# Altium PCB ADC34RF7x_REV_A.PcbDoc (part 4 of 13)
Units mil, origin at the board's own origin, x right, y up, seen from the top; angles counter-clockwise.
Board outline 6250 x 2716.54 mil, 18 copper layers (Top Layer, L2 GND, L3 PWR, L4 GND, L5 PWR/SIG, L6 GND, L7 SIGNAL, L8 GND, L9 GND, L10 SIGNAL, L11 GND, L12 SIGNAL, L13 GND, L14 PWR, L15 GND, L16 PWR/SIG, L16 GND, Bottom Layer), stack 95.314 mil thick; 668 components, 786 nets, 3150 pads, 2020 vias.
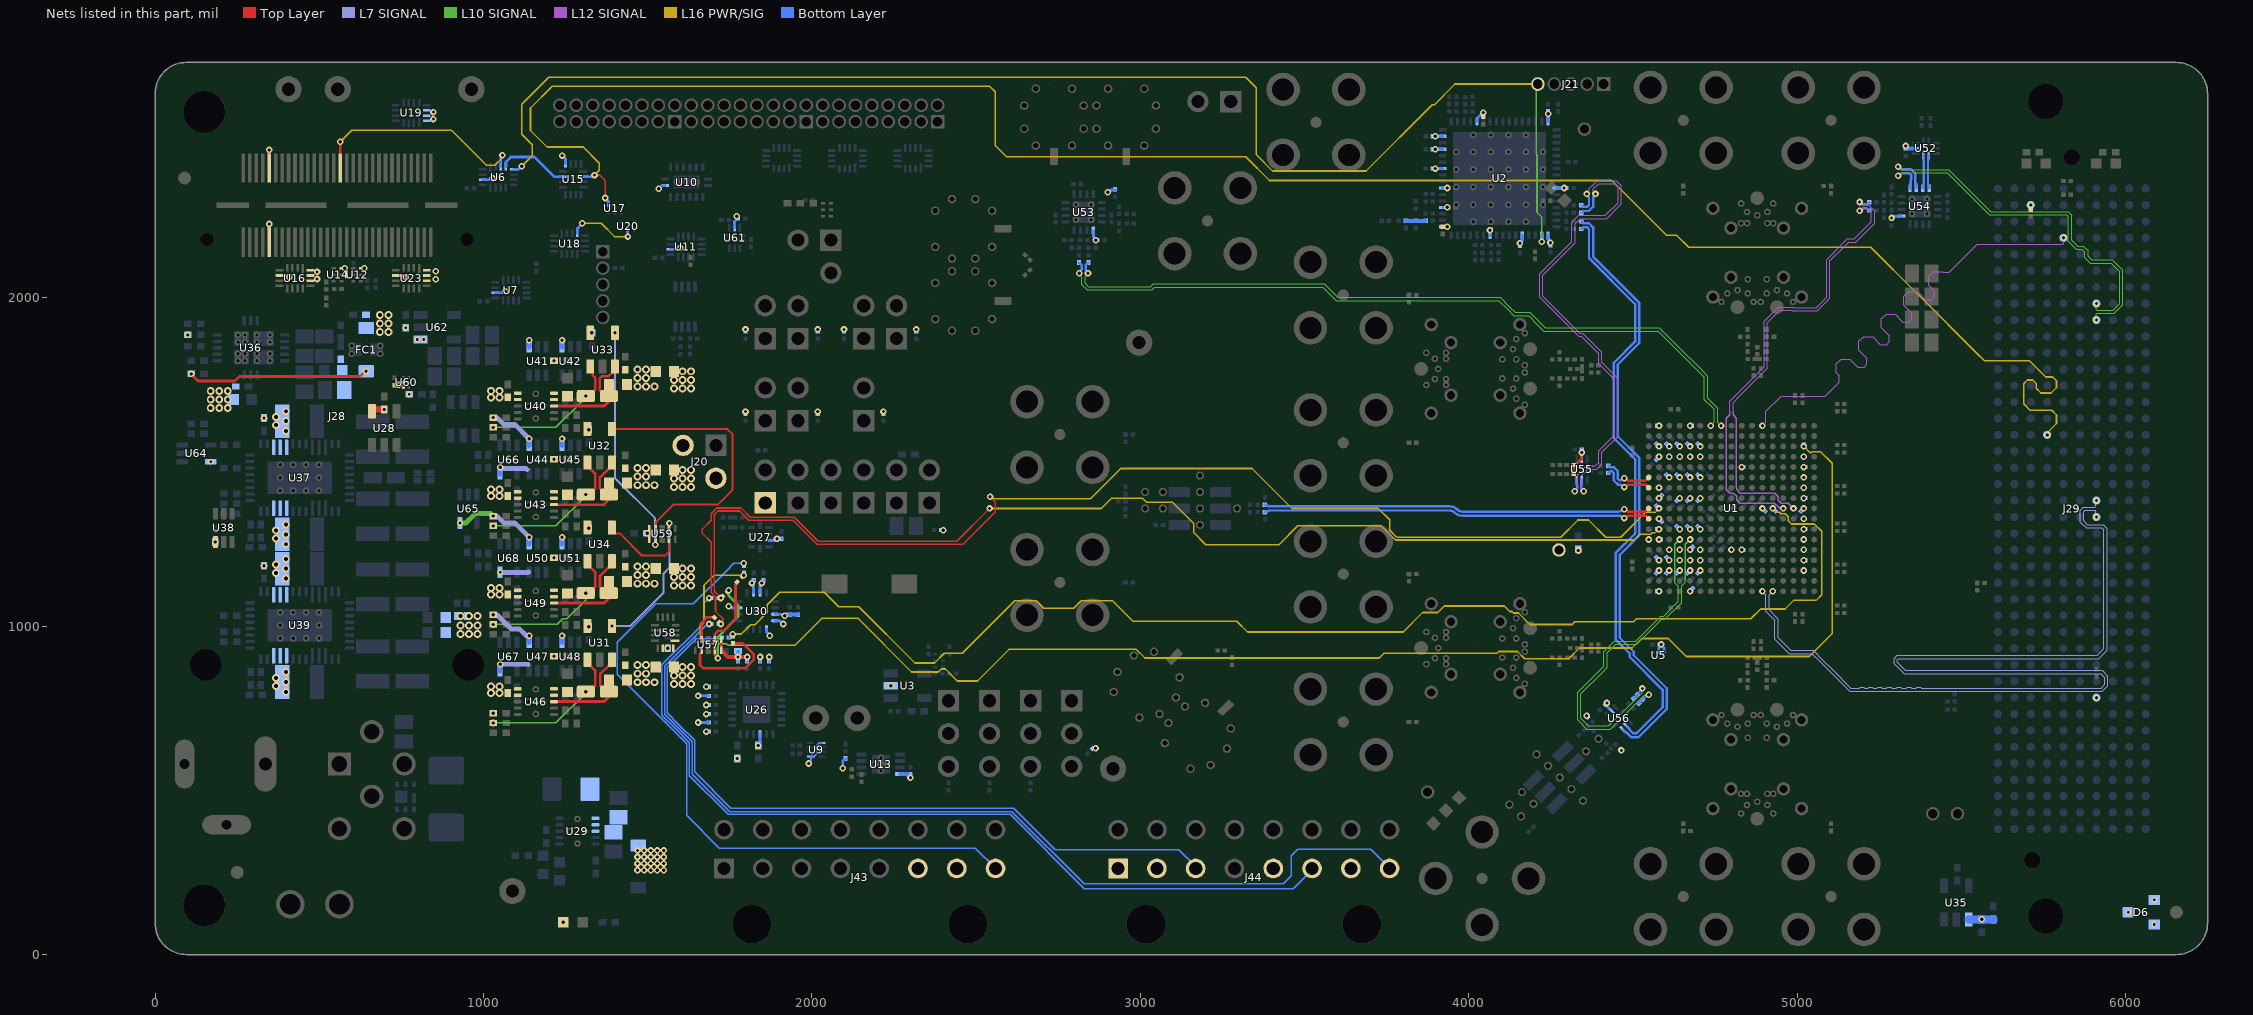
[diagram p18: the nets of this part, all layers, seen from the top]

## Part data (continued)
R202 R203: library part RSMD060312253, "RES 0 OHM JUMPER 0603 SMD", Manufacturer="Panasonic Electronic Components", Operating Temperature="-55°C ~ 155°C", Power (Watts)="0.1W, 1/10W", Ratings=AEC-Q200, Resistance="0 Ω", Supplier Part Number 1=10-ERJ-U030R00VCT-ND, Temperature Coefficient=±200ppm/°C, Tolerance=Jumper
R220 R221 R222 R223: library part RSMD080510615, "RES SMD 0 OHM JUMPER 1/8W 0805", Manufacturer="Panasonic Electronic Components", Operating Temperature="-55°C ~ 155°C", Power (Watts)="0.125W, 1/8W", Ratings=AEC-Q200, Resistance="0 Ω", Supplier Part Number 1=P0.0ACT-ND, Temperature Coefficient=-, Tolerance=Jumper
SH-J19 SH-J20 SH-J24 SH-J25 SH-J26 SH-J27 SH-J30 SH-J34 SH-J38 SH-J39 SH-J40 SH-J45: library part cmp00093, "2 (1 x 2) Position Shunt Connector Black Closed Top 0.100\" (2.54mm) Gold", Alt Manufacturer=-, Manufacturer=Sullins, Supplier Part Number 1=S9001-ND
SW1: library part cmp00291, "SWITCH TACTILE SPST-NO 0.05A 12V", Alt Manufacturer=-, Manufacturer="Würth Elektronik", Supplier Part Number 1=732-7053-1-ND
SW2 SW3 SW4 SW6: library part cmp00353, "Switch Slide SPDT 12V, 500mA", Alt Manufacturer=-, Manufacturer="Wurth Elektronik", Supplier Part Number 1=710-450301014042
T1 T2 T4 T5: library part cmp00063, "Broadband Balun, 500 kHz to 6 GHz", Alt Manufacturer=-, Manufacturer="Marki Microwave"
T3: library part cmp00422, "1:2 CORE & WIRE Transformer, 30 - 6000 MHz, 50Ω", Alt Manufacturer=-, Manufacturer=Mini-Circuits, Supplier Part Number 1=139-TCM2-63WX
T6: library part cmp00381, "1:2 CORE & WIRE Transformer, 10 - 4000 MHz, 50Ω", Alt Manufacturer=-, Manufacturer=Mini-Circuits, Supplier Part Number 1=139-TCM2-43X
TP3: library part cmp00053, "Test Point, Miniature, Orange, TH", Alt Manufacturer=-, Color=Orange, Manufacturer=Keystone, Supplier Part Number 1=36-5003-ND
TP4 TP5 TP9 TP10: library part cmp00051, "Test Point, Miniature, Black TH", Alt Manufacturer=-, Color=Black, Manufacturer=Keystone, Supplier Part Number 1=36-5001-ND
TP6 TP7 TP8: library part cmp00052, "Test Point, Miniature, White, TH", Alt Manufacturer=-, Color=White, Manufacturer=Keystone, Supplier Part Number 1=36-5002-ND
TP11: library part cmp00040, "Test Point, Multipurpose, Red, TH", Alt Manufacturer=-, Color=Red, Manufacturer=Keystone, Supplier Part Number 1=36-5010-ND
TP12: library part cmp00047, "Test Point, Multipurpose, Brown, TH", Alt Manufacturer=-, Color=Brown, Manufacturer=Keystone, Supplier Part Number 1=36-5125-ND
U1: "Quad channel 16-bit 1.5 GSPS RF sampling data converter, FCCSP-289 (ANH0289A)", Alternate Manufacturer="Texas Instruments"
U2: library part cmp00252, "Ultra low-noise JESD204B compliant clock jitter cleaner with integrated 2370 to 2630-MHz VCO0", Alt Manufacturer="Texas Instruments", Alt PartNumber=LMK04828BISQE/NOPB, Color=-, Supplier Part Number 1=296-40278-1-ND
U3: "Open Drain, 1.6V threshold, Nano Power, Wide VIN Voltage Detector with Programmable Delay", Alt Manufacturer=-, Manufacturer="Texas Instruments"
U4: library part cmp00518, "Low-Power Single 2-Input Positive-AND Gate", Color=-, Manufacturer="Texas Instruments", PartNumber=SN74AUP1G08DRYR, Supplier Part Number 1=296-SN74AUP1G08DRYRCT-ND
U5 U60: library part cmp00348, "±0.1°C accurate digital temperature sensor with integrated NV memory, YBG0006AJAP (DSBGA-6)", Alt Manufacturer=-, Manufacturer="Texas Instruments"
U6: "Low-Voltage 4-Bit 1-of-2 FET Multiplexer/Demultiplexe", Color=-, Manufacturer="Texas Instruments", PartNumber=SN74CBTLV3257RSVR, Supplier Part Number 1=296-35586-1-ND
U7 U11: library part SN74CBTLV3257RSV, "Low-Voltage 4-Bit 1-of-2 FET Multiplexer/Demultiplexe", Color=-, Manufacturer="Texas Instruments", Supplier Part Number 1=296-35586-1-ND
U8: library part cmp00344, "Low-Power Single Bus Buffer Gate With Tri-State Output", Alt Manufacturer="Texas Instruments", Color=-
U9: "2-BIT BIDIRECTIONAL VOLTAGE-LEVEL TRANSLATOR, DQE0008A (X2SON-8). Open drain friendly", Alternate Manufacturer="Texas Instruments"
U10: "Bidirectional 4:1, 2-Channel Multiplexer with Injection Current Control", Manufacturer="Texas Instruments"
U12 U14 U17 U20: library part cmp00343, "Low-Power Single Bus Buffer Gate With 3-State Output", Alt Manufacturer="Texas Instruments", Alt PartNumber=SN74LVC1G125DRYT, Color=-
U13: library part cmp00154, "EEPROM 64K 8KX8 1.8V SER EE IND 1/4AWP RPO", Alt Manufacturer=-, Manufacturer=Microchip, Supplier Part Number 1=24LC64FT-I/MNYCT-ND
U15 U16 U18 U19 U22 U23 U24 U25: library part cmp00171, "Translation - Voltage Levels 4-bit dual-supply bus transceiver with 3-state outputs and independent direction control inputs", Alt Manufacturer="Texas Instruments", Alt PartNumber=SN74AXC4T774RSV, Color=-, Supplier Part Number 1=296-24741-1-ND
U21: library part cmp00175, "Dual-Bit Dual-Supply Bus Transceiver With Configurable Voltage Translation And 3-State Outputs", Alt Manufacturer="Texas Instruments", Alt PartNumber=SN74AXCH2T45DCU, Color=-, PartNumber=SN74AVCH2T45DCU
U26: library part CMP-0076018-3, "Low-Voltage 8-Channel I2C Switch With Reset, RGE0024C (VQFN-24)", Alternate Manufacturer="Texas Instruments", Operating Temperature Range="-40 to 85 C"
U27: library part CMP-0081816-1, "16-Bit 860SPS 1-Ch Delta-Sigma ADC With PGA, Oscillator, VREF, Comparator, and I2C, RUG0010A (X2QFN-10)", Alternate Manufacturer="Texas Instruments", Alternate PartNumber=ADS1114IRUGT, Operating Temperature Range="-40 to 125 C", Rating=Catalog
U28 U31 U32 U33 U34: "26V, 350kHz current sense amplifier", Alt Manufacturer="Texas Instruments", Alt PartNumber=INA180B1IDBVT
U29: library part cmp00157, "12V, 5A, 30mΩ eFuse with Adjustable +/-15% Accurate Current Limit, DRC0010J (VSON-10)", Alt Manufacturer=-, Manufacturer="Texas Instruments"
U30: "16-Bit, 4-Channel, 1-kSPS, Delta-Sigma ADC with I2C Interface, RTE0016D (WQFN-16)", Alternate Manufacturer="Texas Instruments", Alternate PartNumber=ADS1119IRTET, Operating Temperature Range="-40 to 125 C"
U35 U62: "150-mA, 30-V, ultra-low-IQ, low-dropout voltage regulator with reverse current protection and enable", Alt Manufacturer=-, Manufacturer="Texas Instruments", Supplier Part Number 1=296-35484-1-ND
U36: library part cmp00201, "3-V to 17-V, 2-A/3-A Low-Noise and Low-Ripple Buck Power Module with Integrated Ferrite Bead Filter Compensation", Alt Manufacturer=-, Manufacturer="Texas Instruments", Max Supply Voltage=17V, Min Supply Voltage=3V, Nominal Supply Current=5mA, Operating Temperature Range="-55°C to +125°C", Output Voltage=0.8-5.5V, PartNumber=TPSM82913RDU, Switching Frequency=1/2.2MHz
U37 U39: library part cmp00235, "4.5-V to 15-V Input, Dual 6-A / Single 12-A Output Power Module", Alt Manufacturer=-, Manufacturer="Texas Instruments", Supplier Part Number 1=296-TPSM5D1806RDBRCT-ND
U38 U41 U44 U47 U50: "128-tap single-channel digital potentiometer (digipot) with I2C interface (address 0101110)", Alt Manufacturer=-, Alternate Manufacturer="Texas Instruments", Alternate PartNumber=TPL0401A-10DCKT
U40 U43 U46 U49: library part cmp00446, "2-A, ultra-low noise ultra-high PSRR RF voltage regulator", Alt Manufacturer=-, Manufacturer="Texas Instruments", PartNumber=TPS7A9601DSCR
U42 U45 U48 U51: "128-tap single-channel digital potentiometer (digipot) with I2C interface (address 0111110)", Alt Manufacturer=-, Alternate Manufacturer="Texas Instruments", Alternate PartNumber=TPL0401B-10DCKT
U52 U55 U56: library part TMUX121NKGR, "2-pF, 3.3-V, 2:1 (SPDT), 2-channel, switch with 1.8-V compatible logic", Manufacturer="Texas Instruments"
U53 U54: library part cmp00271, "Texas Instruments", Color=-, Manufacturer_Part_Number=LMK1D1204RGTR, PartNumber=LMK1D1204RGTT, Supplier Part Number 1=296-LMK1D1204RGTRCT-ND
U57 U59: "3-pA on-state leakage current, 5-V, 4:1, 1-channel precision multiplexer", Alt Manufacturer=-, Manufacturer="Texas Instruments", Supplier Part Number 1=296-53437-2-ND
U58: "Low-voltage 8-bit I²C-bus/SMBus I/O expander with interrupt, reset and agile I/O configuration", Alt Manufacturer=-, Manufacturer="Texas Instruments", Supplier Part Number 1=296-TCAL9538RSVRTR-ND
U61: "2-pF, 3.3-V, 2:1 (SPDT), 2-channel, switch with 1.8-V compatible logic", Manufacturer="Texas Instruments"
U63: "3 Rail Simple Power Sequencer with Fixed Time Delay", Manufacturer="Texas Instruments"
U64 U65 U66 U67 U68: library part cmp00268, "SN74AUP1G08 Low-Power Single 2-Input Positive-AND Gate", Color=-, Manufacturer="Texas Instruments", Supplier Part Number 1=296-19075-1-ND
ZZ1: library part CMP-0003616-3
ZZ2: library part CMP-0077236-1
ZZ3: library part CMP-0077237-1
ZZ4: library part CMP-0077238-1

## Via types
v1: diameter 20, hole 10, Top Layer to Bottom Layer, tented both sides, 1793 vias
v2: diameter 24, hole 12, Top Layer to Bottom Layer, tented both sides, 168 vias
v3: diameter 18, hole 8, Top Layer to Bottom Layer, tented both sides, 59 vias

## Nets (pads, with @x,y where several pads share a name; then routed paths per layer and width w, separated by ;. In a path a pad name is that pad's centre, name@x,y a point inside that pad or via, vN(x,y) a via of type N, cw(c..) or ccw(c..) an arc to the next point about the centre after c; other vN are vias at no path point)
2p3V: C221.2 C222.2 C228.2 C235.2 C242.2 C249.2 FB4.2 FB5.2 U40.1 U40.2 U43.1 U43.2 U46.1 U46.2 U49.1 U49.2
  other v2: 1022.37,796.58 1048.37,796.58 1022.37,816.58 1048.37,816.58 929.64,975.59 955.64,975.59 981.64,975.59 929.64,1002.01 955.64,1002.01 981.64,1002.01 929.64,1030.43 955.64,1030.43 981.64,1030.43 1022.37,1096.58 1048.37,1096.58 1022.37,1116.58 1048.37,1116.58 1022.37,1396.58 1048.37,1396.58 1022.37,1416.58 1048.37,1416.58 1022.37,1696.58 1048.37,1696.58 1022.37,1716.58 1048.37,1716.58
3p3V: C170.1 FB1.2 FC1.1 R112.2 R114.2 | length 553.3
  Top Layer w9: v1(109.72,1767.95) 130.88,1746.8 243.05,1746.8 256.6,1760.34 623.9,1760.34 639.26,1775.71 v1(642.24,1775.71)
3p3V_AUX: D6.1 J29.D32
  other v1: 5911.42,782.27
  other v3: 6087.6,166.23
3p3V_EEPROM: C181.2 D6.3 R211.1 U13.8 | length 80.3
  Bottom Layer w8: v1(2094.07,567.32) 2094.07,589.15 2098.76,593.83 2100.15,593.83 2102.45,596.13 R211.1@2102.45,596.92 ; v1(2299.91,538.04) C181.2@2299.91,548.04
  Bottom Layer w12: U13.8@2268.5,550 2287.96,550 v1(2299.91,538.04)
  other v3: 6008.86,128.83
3p3V_Utility: C41.1 C42.1 C43.1 C44.1 C45.1 C46.1 C47.1 C48.1 C49.1 C50.1 C51.1 C52.1 C61.2 C94.1 C102.1 C103.1 C104.1 C106.1 C107.1 C175.1 C176.1 C177.1 C178.2 C179.2 C182.2 C183.2 C185.2 C186.2 C204.2 C215.2 C233.2 C240.2 C247.2 C254.2 C256.2 C258.2 C263.2 C264.2 D6.2 FC1.3 J28.51 J28.52 J38.1 R66.2 R67.2 R71.2 R72.2 R73.2 R74.2 R79.1 R88.2 R92.2 R93.2 R94.2 R95.2 R96.2 R97.2 R98.2 R99.2 R100.2 R101.2 R102.2 R118.1 R125.1 R131.2 R137.2 R143.2 R149.2 R162.2 R165.2 R189.2 R190.2 R191.2 R192.2 R210.2 R215.2 U2.10 U2.17 U2.21 U2.26 U2.33 U2.36 U2.39 U2.42 U2.45 U2.47 U2.53 U2.64 U5.B1 U5.C1 U6.14 U7.14 U9.1 U9.5 U10.16 U11.14 U12.6 U14.6 U15.13 U16.6 U16.14 U16.15 U16.16 U19.14 U19.15 U19.16 U23.6 U23.14 U23.15 U23.16 U26.21 U27.8 U28.5 U30.1 U30.7 U30.10 U30.11 U30.15 U30.16 U31.5 U32.5 U33.5 U34.5 U38.1 U41.1 U42.1 U44.1 U45.1 U47.1 U48.1 U50.1 U51.1 U52.9 U53.5 U54.5 U55.9 U56.9 U57.5 U57.6 U58.1 U58.14 U58.15 U58.16 U59.5 U59.6 U60.B1 U60.C1 U61.9 U64.5 U65.5 U66.5 U67.5 U68.5 | length 2945.1
  Top Layer w8: U16.6@378.7,2067.76 400.45,2067.76 405.45,2062.76 v1(408.7,2062.76) ; U14.6@567.36,2089.41 v1(577.36,2089.41) ; U12.6@627.05,2089.41 v1(637.05,2089.41) ; C178.2@729.29,1733.83 729.58,1734.12 740.84,1734.12 v1(741.13,1734.41) ; U23.6@733.03,2067.76 754.78,2067.76 759.78,2062.76 v1(763.03,2062.76) ; U59.6@1505.18,1264.12 1505.18,1271.18 1500.48,1275.87 1500.48,1280.52 v1(1498.19,1282.81) 1498.19,1282.94 1505.18,1289.93 U59.5@1505.18,1296.99 ; U57.6@1723.88,959.19 U57.5@1723.88,926.32 1723.88,923.26 U57.5@1725.94,921.2 ; C42.1@3920.96,2216.02 v1(3935.05,2216.04) ; C47.1@4044.13,2550.8 v1(4044.13,2563.74) v1@4044.13,2564.74 ; R190.2@4319.91,1463.74 R189.2@4319.91,1490.75 4324.89,1490.75 4343.25,1509.1 4343.25,1527.35 v1(4344.64,1528.74) ; v1@5331.04,2454.89 v1@5331.04,2461.96 ; v1(741.13,1734.41) 743.42,1732.11 750.49,1732.11 756.37,1726.23 U60.C1@756.65,1726.23 U60.B1@756.65,1741.98 756.37,1741.98 751.09,1736.7 743.42,1736.7 v1(741.13,1734.41)
  Top Layer w11: J28.52@347.2,2169.41 v1(347.2,2224.41) ; J28.51@347.2,2395 v1(347.2,2450)
  Top Layer w12: U57.5@1725.94,921.2 1729,921.2 1744.25,905.95 v1(1775.05,905.95) v1(1802.74,905.95)
  Top Layer w20: U28.5@660.5,1654.13 660.5,1659.88 v1(697.55,1659.88)
  L7 SIGNAL w15: v1(1030,1035) 1030.96,1034.04 1042.32,1034.04 1085.39,990.97 1110.3,990.97 1129.84,971.43 1138.18,971.43 v1(1139.13,970.47) ; v1(1030,1335) 1030.96,1334.04 1042.32,1334.04 1061.86,1314.5 1095.11,1314.5 v1(1139.13,1270.47) ; v1(1030,1635) 1030.96,1634.04 1042.32,1634.04 1061.86,1614.5 1095.11,1614.5 v1@1138.18,1571.43 ; v1(1050.63,883.86) 1135.66,883.86 1136.22,883.3 ; v3(1050.63,1163.86) 1136.22,1163.86 1136.85,1164.49 ; v1@1050.63,1480.18 1129,1480.18 1131.98,1477.19
  L10 SIGNAL w15: v3(928.31,1314) 945.89,1314 974.44,1342.56 1022.44,1342.56 v1(1030,1335)
  Bottom Layer w4: R79.1@2855,627.06 2855.61,627.06 2856.31,627.76 v1(2863.7,627.76)
  Bottom Layer w6: v1(1990.28,581.72) 1990.28,584.72 1997.39,591.83 U9.1@1997.39,602.63 2005.64,602.63 2013.51,610.49 2013.51,636.33 2021.09,643.91 2030.8,643.91 U9.5@2030.85,643.96
  Bottom Layer w8: U6.14@997.49,2359.25 1019.25,2359.25 1024.25,2364.25 v1(1027.49,2364.25) ; U7.14@1036.12,2015 1057.87,2015 1062.87,2020 v1(1066.12,2020) ; v1(1239.74,2432.87) 1239.74,2432.09 1242.04,2429.79 1242.82,2429.79 1249.74,2422.87 U15.13@1249.74,2407.87 ; v1(1533.39,2332.09) 1534.8,2332.09 1544.07,2341.36 1552.66,2341.36 U10.16@1553.39,2342.09 ; U11.14@1569.13,2147.28 1590.89,2147.28 1595.89,2152.28 v1(1599.13,2152.28) ; v1(1653.34,706.47) 1673.34,706.47 R93.2@1685.43,706.48 ; v1(1653.34,787.52) 1673.34,787.52 R96.2@1685.43,787.54 ; R92.2@1678.36,678.8 R92.2@1685.43,678.8 ; R94.2@1678.36,732.17 R94.2@1685.43,732.17 ; R95.2@1678.35,759.84 R95.2@1685.43,759.85 ; R97.2@1678.36,815.22 R97.2@1685.43,815.22 ; U61.9@1764.47,2213.57 1764.47,2232.47 1773.67,2241.68 C182.2@1774.46,2241.68 1771.45,2244.7 v1(1771.45,2247.74) ; R98.2@1775.07,892.86 R98.2@1775.07,899.93 ; v1(1775.05,905.95) C176.1@1775.05,923.95 ; R165.2@1797.76,1647.41 v1(1797.76,1653.41) ; R73.2@1797.76,1897.41 v1(1797.76,1903.41) ; R99.2@1802.75,892.86 R99.2@1802.75,899.93 ; R100.2@1842.12,892.86 R100.2@1842.12,899.93 ; R101.2@1869.81,892.86 R101.2@1869.81,899.93 ; R162.2@2017.76,1647.41 v1(2017.76,1653.41) ; R74.2@2017.76,1897.41 v1(2017.76,1903.41) ; R72.2@2097.76,1897.41 v1(2097.76,1903.41) ; R88.2@2217.76,1647.41 v1(2217.76,1653.41) ; R71.2@2317.76,1897.41 v1(2317.76,1903.41) ; R215.2@2394.27,1292.17 v1(2400.27,1292.17) ; C44.1@3890.96,2393.19 v1(3898.05,2393.2) ; C45.1@3890.96,2452.24 v1(3898.05,2452.26) ; C46.1@3890.96,2491.61 v1(3898.05,2491.63) ; U2.33@3928.03,2216.02 U2.33@3920.96,2216.02 v1(3935.05,2216.04) ; U2.36@3928.03,2275.08 U2.36@3920.96,2275.08 v1(3935.05,2275.09) ; U2.39@3928.03,2334.13 U2.39@3920.96,2334.13 v1@3935.04,2334.14 ; U2.53@4025.29,2536.89 4026.21,2537.81 4026.21,2546.83 v1@4044.13,2564.74 ; C52.1@4156.08,2158.43 v1(4156.07,2165.52) ; v1(4241.84,2559.8) C49.1@4241.82,2566.89 ; C51.1@4248.82,2160.43 v1(4248.81,2167.52) ; v1(4290.33,2334.12) C48.1@4297.42,2334.13 ; U55.9@4344.64,1508.74 v1(4344.64,1528.74) C263.2@4344.64,1538.27 ; v1(4358.93,726.7) R191.2@4361.93,723.7 ; C264.2@4415.91,760.86 v1(4420.91,765.88) ; C264.2@4418.08,763.06 4417.56,762.53 4417.56,759.26 U56.9@4429.5,747.32 ; C264.2@4420.91,761.42 v1(4420.91,765.88) ; R192.2@4462.07,624.52 v1(4465.07,621.52) ; U5.B1@4578.88,919.29 4578.88,933.6 C179.2@4586.75,941.48 ; C179.2@4581.75,944.29 v1(4586.75,944.29) C179.2@4586.75,941.48 ; U5.C1@4594.63,919.29 4594.63,933.6 C179.2@4586.75,941.48 ; v1(5287.73,2243) 5288.94,2243 5294.52,2248.58 U54.5@5317.73,2248.58
  Bottom Layer w9: v1(1747.16,1060.85) 1750.14,1060.85 1755.14,1055.85 U30.7@1777.16,1055.85 ; U30.10@1822.44,1101.13 1822.44,1123.15 1817.44,1128.15 v1(1817.44,1131.13) 1817.44,1133.15 1823.1,1138.82 C185.2@1823.1,1139.6 ; v1(1837,636.2) 1842.12,641.32 U26.21@1842.12,671.2 ; U30.11@1842.12,1101.13 1842.12,1123.15 1847.12,1128.15 v1(1847.12,1131.13) 1847.12,1133.15 1852.79,1138.82 C186.2@1852.79,1139.6 ; U30.1@1861.81,990.89 1861.89,990.8 1861.89,981.8 1871.81,971.89 v1(1871.81,970.89) ; U27.8@1868.71,1261.07 1885.74,1261.07 1890.74,1266.07 v1(1893.71,1266.07) C183.2@1907.71,1266.07 ; U30.16@1887.4,1016.48 1887.48,1016.39 1901.49,1016.39 1911.4,1006.48 v1(1912.4,1006.48) ; U30.15@1887.4,1036.17 1909.42,1036.17 1914.42,1031.17 v1(1917.4,1031.17) ; U53.5@2856.85,2205.32 2856.85,2185.78 2864.34,2178.29 v1(2864.34,2175.32) C61.2@2869.34,2175.32
  Bottom Layer w10: v1(2900.65,2321.19) 2903.35,2321.19 2909.91,2327.74 2921.66,2327.74 2922.96,2329.04 R210.2@2922.96,2329.83 ; v1@3898.06,2393.19 U2.42@3920.96,2393.19 ; v1@3898.06,2452.24 U2.45@3920.96,2452.24 ; v1@3898.06,2491.61 U2.47@3920.96,2491.61 ; U2.26@4064.66,2190.43 v1(4064.66,2205.43) v1@4064.66,2210.43 ; v1(4156.07,2165.52) 4156.07,2168.22 4163.08,2175.24 U2.21@4163.08,2190.43 ; U2.17@4241.82,2190.43 4241.82,2177.21 4248.81,2170.22 v1(4248.81,2167.52) ; U2.64@4241.82,2536.89 v1(4241.84,2559.8) ; U2.10@4267.42,2334.13 v1(4290.33,2334.12)
  Bottom Layer w12: v1(1917.4,1031.17) 1919.56,1031.17 1923.38,1034.98 R66.2@1932.4,1034.98 R67.2@1957.4,1034.98 ; C256.2@5331.04,2454.89 U52.9@5361.04,2454.89
  Bottom Layer w15: U67.5@1050.63,863.86 v1(1050.63,883.86) ; U66.5@1050.63,1463.86 v1(1050.63,1483.86) ; U47.1@1139.13,950.47 v1(1139.13,970.47) ; U50.1@1139.13,1250.47 v1(1139.13,1270.47) ; U44.1@1139.13,1550.47 v1(1139.13,1570.47) ; U41.1@1139.13,1850.47 v1(1139.13,1870.47) ; U48.1@1239.13,950.47 v1(1239.13,970.47) ; U51.1@1239.13,1250.47 v1(1239.13,1270.47) ; U45.1@1239.13,1550.47 v1(1239.13,1570.47) ; U42.1@1239.13,1850.47 v1(1239.13,1870.47)
  other v1: 1773.07,596.83 1678.34,678.78 1678.34,732.15 1030,735 1678.34,759.83 1678.34,815.21 1842.11,905.95 1869.79,905.95 1214.61,907.95 1561.46,932.35 1320.5,998.21 331.53,1184.01 1214.61,1207.95 183.42,1255.95 1320.5,1298.21 1214.61,1507.95 1320.5,1598.21 331.53,1633.5 1214.61,1807.95 1329.5,1893.21 854.82,2056.26 493.19,2057.01 493.19,2078.5 854.82,2080.26 3935.05,2334.15 5331.05,2461.98 847.52,2543.94 847.52,2565.43
  other v2: 684.2,1895.3 710.2,1895.3 684.2,1921.3 710.2,1921.3 684.2,1947.3 710.2,1947.3
  other v3: 6087.6,91.43 169.01,1500.59
12V: C58.2 C95.2 C96.2 C126.2 C128.1 C171.2 C172.2 C173.2 C174.2 D3.1 D5.1 F1.1 R113.1 R179.2 R224.2 R225.1 U29.6 U29.7 U29.8 U35.1 U36.18 U37.4 U37.5 U37.6 U37.33 U37.34 U37.35 U39.4 U39.5 U39.6 U39.33 U39.34 U39.35 U62.1 | length 75.1
  Bottom Layer w24: U35.1@5522.4,107 v1(5562.52,107) R179.2@5597.52,107
  other v1: 1243.15,98.59 1469,257 1489,257 1509,257 1529,257 1549,257 1469,277 1489,277 1509,277 1529,277 1549,277 1469,297 1489,297 1509,297 1529,297 1549,297 1469,317 1489,317 1509,317 1529,317 1549,317 99.72,1886.69
  other v2: 397.94,799.76 367.94,817.26 397.94,829.76 367.94,842.26 397.94,859.76 397.94,1144.8 367.94,1162.3 397.94,1174.8 367.94,1187.3 397.94,1204.8 397.94,1249.25 367.94,1266.75 397.94,1279.25 367.94,1291.75 397.94,1309.25 397.94,1594.29 367.94,1611.79 397.94,1624.29 367.94,1636.79 397.94,1654.29 169.26,1663.64 195.26,1663.64 221.26,1663.64 169.26,1689.64 195.26,1689.64 221.26,1689.64 169.26,1715.64 195.26,1715.64 221.26,1715.64
  other v3: 773.6,1705.75 798.07,1872.9 818.07,1872.9 763.07,1908.33
\M2C-PRESENT: J29.H2 R86.2 | length 14
  Top Layer w8: R86.2@5711.42,2268.29 v1(5711.42,2282.27)
ADC_CLK_N: C18.2 C19.2 U1.U9 | length 1183.3
  Top Layer w7.4: v1(4473.75,1356.02) 4477.09,1356.02 4484.39,1348.72 4538.48,1348.72 U1.U9@4548.03,1358.27
  Bottom Layer w7.4: C18.2@3379.28,1369.6 3379.61,1369.28 ccw(c3385.1,1374.77) 3385.1,1367 3386.53,1367 cw(c3386.53,1362.69) 3389.58,1365.74 ccw(c3392.63,1368.79) 3392.63,1364.48 3942.73,1364.48 cw(c3942.73,1333.33) 3964.75,1355.36 ccw(c3980.78,1371.38) 3980.78,1348.72 4456.13,1348.72 ccw(c4456.13,1365.59) 4468.06,1353.66 cw(c4473.75,1347.97) v1(4473.75,1356.02)
ADC_CLK_P: C22.2 C23.1 U1.U10 | length 1183.3
  Top Layer w7.4: v1(4473.75,1329.02) 4477.09,1329.02 4484.39,1336.32 4538.48,1336.32 U1.U10@4548.03,1326.77
  Bottom Layer w7.4: C22.2@3379.28,1346.96 3379.61,1347.28 cw(c3385.1,1341.79) 3385.1,1349.56 3386.53,1349.56 ccw(c3386.53,1353.86) 3389.58,1350.82 cw(c3392.63,1347.77) 3392.63,1352.08 3942.73,1352.08 cw(c3942.73,1333.33) 3955.99,1346.59 ccw(c3980.78,1371.38) 3980.78,1336.32 4456.13,1336.32 cw(c4456.13,1319.45) 4468.06,1331.38 ccw(c4473.75,1337.07) v1(4473.75,1329.02)
ADC_JESDCLK_CORECLK_N: J29.D9 U54.10 | length 1191.7
  L10 SIGNAL w3.5: v1(5307.57,2398.66) 5309.23,2398.66 5317.73,2390.16 5461.37,2390.16 5589.26,2262.27 5825.21,2262.27 5836.17,2251.31 5836.17,2175.66 5854.81,2157.02 5871.67,2157.02 5886.17,2142.52 5886.17,2125.66 5896.83,2115 5960.29,2115 5992,2083.29 5992,1978.13 5986.17,1972.29 5986.17,1972.02 5966.42,1952.27 5913.47,1952.27 5911.42,1950.22 v1(5911.42,1932.27)
  Bottom Layer w7.4: v1(5307.57,2398.66) 5310.9,2398.66 5318.2,2391.36 5346.67,2391.36 5359.65,2378.37 5359.65,2360.96
  Bottom Layer w8: 5359.65,2360.96 5359.65,2349.57 5362.28,2346.95 5362.28,2333.96 U54.10@5363,2333.24
ADC_JESDCLK_CORECLK_P: J29.D8 U54.9 | length 1138
  L10 SIGNAL w3.5: v1(5307.57,2371.66) 5309.23,2371.66 5317.73,2380.16 5457.23,2380.16 5585.12,2252.27 5821.06,2252.27 5826.17,2247.16 5826.17,2171.52 5850.67,2147.02 5867.53,2147.02 5876.17,2138.38 5876.17,2121.52 5892.68,2105 5956.15,2105 5971.92,2089.22 5982,2079.15 5982,1982.27 5976.17,1976.44 5976.17,1976.16 5962.28,1962.27 5913.47,1962.27 5911.42,1964.32 v1(5911.42,1982.27)
  Bottom Layer w7.4: v1(5307.57,2371.66) 5310.9,2371.66 5318.2,2378.96 5341.53,2378.96 5347.26,2373.23 5347.26,2360.96
  Bottom Layer w8: U54.9@5343.31,2333.24 5344.03,2333.96 5344.03,2346.95 5346.65,2349.57 5346.65,2360.96
ADC_JESDCLK_MGTREFCLK_N: U52.6 U54.12 | length 102.2
  Bottom Layer w7.4: U52.6@5400.41,2433.24 5400.17,2433 5400.17,2418.45 5398.73,2417.02 5398.73,2343.97 5402.38,2340.32 U54.12@5402.38,2333.24
ADC_JESDCLK_MGTREFCLK_P: U52.7 U54.11 | length 102.2
  Bottom Layer w7.4: U54.11@5382.69,2333.24 5382.69,2340.32 5386.34,2343.97 5386.34,2417.02 5384.9,2418.45 5384.9,2433 U52.7@5384.66,2433.24
ADC_JESDCLK_N: C262.2 U1.C9 | length 1411.5
  L12 SIGNAL w3.5: 4805.4,1654.43 4805.4,1655.13 4805.15,1655.38 4805.15,1680.55 4825.99,1701.39 4849.72,1725.11 4909.52,1784.91 4909.52,1924.05 4946.91,1961.45 4984.22,1961.45 4985.72,1959.95 5061.85,1959.95 5099.93,1998.02 5099.93,2111.93 5146.12,2158.13 5156.97,2168.97 5178.22,2168.97 5228.75,2219.51 5236.4,2227.16 5236.4,2263.35 5233.47,2266.28 5216.72,2283.03 5194.08,2283.03 5192.03,2285.08 v1@5192.03,2291.53
  L12 SIGNAL w4: 4805.4,1654.43 4805.4,1643.08 4815.5,1632.99 4815.5,1421.51 4815.5,1416.04 4826.28,1405.26 4931.7,1405.26 4942.48,1394.48 4942.48,1383.55 4951.27,1374.76 4973.83,1374.76 4988.98,1359.62 v1(4988.98,1358.27)
  Bottom Layer w7.4: v1(5190.36,2291.53) 5193.7,2291.53 5201,2284.23 5212.57,2284.23 5218.89,2290.55 C262.2@5219.68,2290.55
ADC_JESDCLK_P: C261.2 U1.D9 | length 1393.8
  L12 SIGNAL w3.5: 4794.9,1654.43 4794.9,1655.13 4795.15,1655.38 4795.15,1684.69 4815.99,1705.53 4845.58,1735.11 4899.52,1789.05 4899.52,1928.2 4935.41,1964.09 4938.34,1967.02 4942.77,1971.45 4988.36,1971.45 4989.86,1969.95 5057.71,1969.95 5089.93,2002.16 5089.93,2116.07 5136.12,2162.27 5152.83,2178.97 5174.07,2178.97 5226.4,2231.3 5226.4,2259.21 5212.58,2273.03 5194.08,2273.03 5192.03,2270.98 v1@5192.03,2264.53
  L12 SIGNAL w4: 4794.9,1654.43 4794.9,1643.08 4784.81,1632.99 4784.81,1415.23 4794.91,1405.14 4805.84,1405.14 4815.75,1395.23 4815.75,1384.3 4825.28,1374.76 4930.7,1374.76 4947.2,1358.27 v1(4957.48,1358.27)
  Bottom Layer w7.4: v1(5190.36,2264.53) 5193.7,2264.53 5201,2271.83 5212.57,2271.83 5218.89,2265.5 C261.2@5219.68,2265.5
ADC_JESDCLKIN_LMK_N: R55.2 U56.4 | length 1835.4
  Bottom Layer w7.4: R55.2@4342.46,2209.54 4343.25,2209.54 4348.37,2214.66 4360.65,2214.66 4366.37,2208.94 4366.37,2120.66 4506.73,1980.3 4506.73,1866.5 4441.6,1801.36 4441.6,1573.19 4506.73,1508.06 4506.73,1281.32 4447.53,1222.11 4447.53,959.58 4490.34,916.76 4490.34,905.99 4590.67,805.66 4590.67,753.03 4511.22,673.59 4500.82,673.59 4489.83,684.58 4489.83,686.61 4479.54,696.89 U56.4@4479.54,697.23
ADC_JESDCLKIN_LMK_P: R54.2 U56.5 | length 1886.8
  Bottom Layer w7.4: R54.2@4342.46,2232.19 4343.25,2232.19 4348.37,2227.06 4365.79,2227.06 4378.77,2214.08 4378.77,2125.79 4519.13,1985.43 4519.13,1861.36 4454,1796.23 4454,1578.33 4519.13,1513.19 4519.13,1276.18 4459.93,1216.97 4459.93,964.71 4502.74,921.9 4502.74,911.12 4603.07,810.79 4603.07,747.9 4516.36,661.19 4495.68,661.19 4481.06,675.81 4479.03,675.81 4468.74,686.09 U56.5@4468.41,686.09
ADC_JESDCLKIN_N: C68.1 R180.1 U1.P12 | length 1032.8
  L10 SIGNAL w3.5: v1@4538.97,789.98 4534.82,789.98 4494.48,749.64 4431.15,686.3 4360.14,686.3 4331.79,714.66 4331.79,798.28 4406.76,873.25 4411.97,878.46 4411.97,922.55 4443.71,954.29 4507.99,954.29 4584.28,1030.58 4593.52,1030.58 4638.27,1075.33 4638.27,1121.19 4627.52,1131.94 4627.52,1138.81
  L10 SIGNAL w4: 4627.52,1138.81 4627.52,1248.78 v1(4642.52,1263.78)
  Bottom Layer w7.4: C68.1@4517.88,764.57 R180.1@4529.88,776.57 4542.06,788.75 4545.61,788.75 v1(4548.02,791.16)
ADC_JESDCLKIN_P: C65.1 R180.2 U1.N12 | length 1016.4
  L10 SIGNAL w3.5: v1(4528.93,810.25) 4527.75,809.07 4527.75,797.05 4490.34,759.64 4427,696.3 4364.28,696.3 4341.79,718.8 4341.79,794.14 4410.9,863.25 4421.97,874.32 4421.97,918.41 4447.85,944.29 4512.13,944.29 4588.42,1020.58 4597.66,1020.58 4648.27,1071.19 4648.27,1113.99 ; 4648.27,1115.07 4648.27,1122.68 4659.02,1133.43 4659.02,1138.81
  L10 SIGNAL w4: 4659.02,1138.81 4659.02,1248.78 v1(4674.02,1263.78)
  Bottom Layer w7.4: C65.1@4502.29,780.16 R180.2@4514.29,792.16 4514.29,793.89 4528.93,808.53 v1(4528.93,810.25)
ADC_SDO_VADJ: U18.4 U20.2 | length 211.8
  L16 PWR/SIG w5: v1(1300.76,2226.5) 1358.5,2226.5 1398.82,2186.18 v1(1439.68,2186.18)
  Bottom Layer w8: U18.4@1285.76,2196.5 1285.76,2211.5 v1(1300.76,2226.5) ; v1(1439.68,2186.18) U20.2@1439.68,2206.18
ADC_SYSREF_LMK_N: R61.2 U55.5 | length 1472.3
  L12 SIGNAL w3.5: v1(4323.27,1410.62) 4329.72,1410.62 4331.77,1412.68 4331.77,1461.2 4348.49,1477.93 4358.49,1487.93 4386.07,1487.93 4395.32,1497.18 4395.32,1533.42 4444.96,1583.07 4444.96,1749.75 4413.67,1781.05 4395.32,1799.4 4395.32,1829.61 4342.45,1882.47 4334.55,1882.47 4279.97,1937.06 4216.08,2000.95 4216.08,2072.98 4314.13,2171.03 4314.13,2229.59 4335.7,2251.16 4416.57,2251.16 4455,2289.59 4455,2336.62 4444.96,2346.66 4395.32,2346.66 4383.05,2334.39 4382.77,2334.39 4377.57,2329.19 4377.57,2326.29 4386.07,2317.79 v1(4386.07,2316.12)
  Bottom Layer w7.4: v1(4323.27,1410.62) 4323.27,1413.96 4330.57,1421.26 4330.57,1429.53 4329.13,1430.97 4329.13,1445.51 U55.5@4328.89,1445.75 ; R61.2@4342.46,2258.91 4343.25,2258.91 4348.37,2264.03 4365.79,2264.03 4378.77,2277.02 4378.77,2305.49 4386.07,2312.79 v1(4386.07,2316.12)
ADC_SYSREF_LMK_P: R58.2 U55.4 | length 1484.9
  L12 SIGNAL w3.5: v1(4350.27,1410.62) 4343.82,1410.62 4341.77,1412.68 4341.77,1457.06 4358.49,1473.79 4362.63,1477.93 4390.21,1477.93 4405.32,1493.03 4405.32,1529.28 4454.96,1578.93 4454.96,1753.89 4405.32,1803.54 4405.32,1833.75 4346.59,1892.47 4338.69,1892.47 4284.11,1947.06 4226.08,2005.09 4226.08,2068.84 4318.27,2161.03 4324.13,2166.89 4324.13,2225.44 4339.85,2241.16 4420.71,2241.16 4465,2285.44 4465,2340.76 4462.07,2343.69 4449.11,2356.66 4391.18,2356.66 4378.91,2344.39 4378.63,2344.39 4367.57,2333.33 4367.57,2326.29 4359.07,2317.79 v1(4359.07,2316.12)
  Bottom Layer w7.4: R58.2@4342.46,2281.56 4343.25,2281.56 4348.37,2276.43 4360.65,2276.43 4366.37,2282.16 4366.37,2305.49 4359.07,2312.79 v1(4359.07,2316.12) ; U55.4@4344.64,1445.75 4344.4,1445.51 4344.4,1430.97 4342.97,1429.53 4342.97,1421.26 4350.27,1413.96 v1(4350.27,1410.62)
ADC_SYSREF_N: R204.2 U1.U6 | length 164.9
  Top Layer w7.4: v1(4473.75,1450.51) 4477.09,1450.51 4484.39,1443.21 4538.48,1443.21 U1.U6@4548.03,1452.76
  Bottom Layer w7.4: R204.2@4424.56,1488.55 4425.35,1488.55 4430.45,1483.45 4442.75,1483.45 4453.94,1472.25 4453.94,1448.83 4458.28,1444.49 4464.41,1444.49 4470.42,1450.51 v1(4473.75,1450.51)
ADC_SYSREF_P: R205.2 U1.U7 | length 165.7
  Top Layer w7.4: v1(4473.75,1423.51) 4477.09,1423.51 4484.39,1430.81 4538.48,1430.81 U1.U7@4548.03,1421.26
  Bottom Layer w7.4: R205.2@4424.56,1465.95 4425.35,1465.95 4430.45,1471.05 4437.21,1471.05 4441.54,1466.71 4441.54,1443.69 4454.43,1430.81 4463.12,1430.81 4470.42,1423.51 v1(4473.75,1423.51)
ADC_SYSREFOUT_N: C260.2 U1.L1 | length 2261.6
  L10 SIGNAL w3.5: v1(2813.81,2074.45) 2813.81,2072.78 2822.31,2064.28 2822.31,2039.57 2837.98,2023.89 3035.96,2023.89 3044.24,2032.17 3555.42,2032.17 3590.43,1997.16 3596.61,1990.98 3877.74,1990.98 4091.6,1990.98 4116.79,1965.79 4137.53,1945.05 4182.21,1945.05 4208.99,1918.27 4228.99,1898.27 4576.72,1898.27 4632.81,1842.18 4695.97,1779.02 4717.8,1757.19 4717.8,1689.75 4737.01,1670.54 4747.76,1659.8 4747.76,1620.98 v1(4737.01,1610.24)
  Bottom Layer w7.4: C260.2@2812.79,2107.27 2812.79,2106.48 2815.39,2103.88 2816.78,2103.88 2821.11,2099.55 2821.11,2085.08 2813.81,2077.78 v1(2813.81,2074.45)
ADC_SYSREFOUT_P: C259.2 U1.K1 | length 2261.6
  L10 SIGNAL w3.5: v1(2840.81,2074.45) 2840.81,2072.78 2832.31,2064.28 2832.31,2043.71 2842.13,2033.89 3031.82,2033.89 3040.1,2042.17 3559.56,2042.17 3597.5,2004.23 3600.76,2000.98 4095.74,2000.98 4123.86,1972.86 4141.67,1955.05 4186.35,1955.05 4216.06,1925.34 4233.14,1908.27 4580.86,1908.27 4642.81,1846.32 4703.04,1786.09 4727.8,1761.33 4727.8,1693.9 4744.08,1677.61 4757.76,1663.94 4757.76,1641 4757.76,1636.89 4757.76,1620.98 v1(4768.5,1610.24)
  Bottom Layer w7.4: v1(2840.81,2074.45) 2840.81,2077.78 2833.51,2085.08 2833.51,2099.55 2837.85,2103.88 2839.24,2103.88 2841.84,2106.48 C259.2@2841.84,2107.27
ADC_VCM: C92.1 C93.2 PP5.1 U1.T7 U1.T12 | length 4.7
  Bottom Layer w9: v1(4579.53,1263.78) C93.2@4584.25,1263.78
  other v1: 4333.91,1230.32 4579.53,1421.26
AVDD12: C111.2 C121.2 C123.2 C125.2 C127.2 C129.2 C138.2 C143.2 C144.2 C145.2 C146.2 C147.2 C149.2 C150.2 C151.2 C152.2 C155.2 C158.2 C159.2 C160.2 C161.2 C169.2 C230.2 FB2.2 FB6.2 J20.2 NT2.2 U1.B3 U1.B4 U1.B5 U1.B6 U1.B7 U1.B8 U1.B9 U1.B10 U1.B11 U1.B12 U1.B13 U1.B14 U1.B15 U1.F9 U1.M3 U1.M4 U1.M8 U1.M11 U1.M14 U1.M15 U1.N3 U1.N4 U1.N8 U1.N11 U1.N14 U1.N15 U1.P3 U1.P4 U1.P8 U1.P11 U1.P14 U1.P15 U1.R3 U1.R4 U1.R14 U1.R15 | length 203.2
  L16 PWR/SIG w4: v1(5020.47,1547.24) NT2.2@5028.96,1538.76
  Bottom Layer w8: C149.2@4603.07,1161.34 v1(4611.02,1169.29) ; C155.2@4603.07,1208.72 v1(4611.02,1200.76) ; C161.2@4603.07,1555.2 v1(4611.02,1547.24) ; C150.2@4634.57,1161.34 v1(4642.52,1169.29) ; C143.2@4634.57,1303.23 v1(4642.52,1295.28) ; C138.2@4634.57,1381.81 v1(4642.52,1389.76) ; C160.2@4634.57,1555.2 v1(4642.52,1547.24) ; C151.2@4666.06,1161.34 v1(4674.02,1169.29) ; C144.2@4666.06,1303.23 v1(4674.02,1295.28) ; C147.2@4666.06,1381.81 v1(4674.02,1389.76) ; C159.2@4666.06,1555.2 v1(4674.02,1547.24) ; C152.2@4697.56,1161.34 v1(4705.51,1169.29) ; C145.2@4697.56,1303.23 v1(4705.51,1295.28) ; C146.2@4697.56,1381.81 v1(4705.51,1389.76) ; C158.2@4697.56,1555.2 v1(4705.51,1547.24) ; v1(4894.49,1358.27) C111.2@4902.44,1350.31 ; C121.2@5012.52,1350.31 v1(5020.47,1358.27)
  other v1: 5020.47,1169.29 4642.52,1200.76 4674.02,1200.76 4705.51,1200.76 5020.47,1200.76 5020.47,1232.28 5020.47,1263.78 5020.47,1295.28 5020.47,1326.77 5020.47,1389.76 5020.47,1421.26 5020.47,1452.76 5020.47,1484.25 4611.02,1515.75 4642.52,1515.75 4674.02,1515.75 4705.51,1515.75 5020.47,1515.75
  other v2: 1468.86,1729.11 1494.86,1729.11 1520.86,1729.11 1468.86,1755.11 1494.86,1755.11 1468.86,1781.61 1494.86,1781.11
AVDD12_I2C_SENSE: R171.2 U57.7 | length 213.7
  Top Layer w8: U57.7@1704.2,959.19 1704.2,975.3 1715.06,986.17 1731.71,986.17 1767.17,1021.63 1767.17,1126.44 1772.34,1131.61 R171.2@1772.34,1134.86
AVDD12_I-SNS: U33.4 U59.7 | length 713.2
  Top Layer w6: v1(1522.9,1247.86) 1523.93,1248.89 1523.93,1263.18 U59.7@1524.86,1264.12
  L7 SIGNAL w6: v1(1400.13,1893.18) 1400.13,1451.09 1522.9,1328.32 v1(1522.9,1247.86)
AVDD12_IN: C229.2 R106.1 R133.2 U33.1 U40.9 U40.10 | length 437.8
  Top Layer w8: v1(1311.5,1700.51) 1321.54,1700.51 1340.08,1719.05 1340.08,1756.75 1332.93,1763.9 1332.93,1783.21 U33.1@1325.33,1790.82
  L10 SIGNAL w4: v1(1030,1605) 1220.39,1605 1306.38,1691 1306.38,1691.07 1311.5,1696.18 v1(1311.5,1700.51)
AVDD12_OUT: FB6.1 R106.2 U33.3 U40.8 | length 327.7
  Top Layer w8: R106.2@1379.72,1698.26 R106.2@1381.97,1700.51 1372.63,1700.51 1353.84,1719.31 1353.84,1754.21 1360.79,1761.16 1381.27,1761.16 1392.32,1772.21 1392.32,1783 U33.3@1400.13,1790.82
  Top Layer w9: U40.8@1214.61,1669.8 1366.73,1669.8 1379.72,1682.79 R106.2@1379.72,1698.26
AVDD12_SENSE: NT2.1 R42.1 R171.1 | length 4632.9
  L16 PWR/SIG w5: v1(1792.74,1155.26) 1701.78,1155.26 1671.31,1124.79 1671.31,1079.09 1671.31,1016.98 1659.88,1005.55 1659.88,967.61 1681.67,945.82 1740.21,945.82 1744.64,941.39 1948.67,941.39 2031.76,1024.47 2139.23,1024.47 2303.25,860.45 2385.12,860.45 2394.12,869.45 2406.54,869.45 2423.71,852.27 2443.04,832.95 2504.22,832.95 2600.33,929.06 2988.07,929.06 3014.22,902.91 3727.2,902.91 3742.08,917.79 4086,917.79 4091.03,922.81 4148.67,922.81 4171.04,900.44 4304.82,900.44 4337.59,933.21 4497.46,933.21 4526.54,962.29 4607.43,962.29 4662.18,907.54 5037.3,907.54 5107,977.24 5107,1495.69 5071.45,1531.25 5045.55,1531.25 5043.08,1528.78 5038.94,1528.78 NT2.1@5031.79,1535.93
AVDD12_uFit: FB2.1 J43.11 J43.13
  other v2: 1580.08,1723.95 1606.08,1723.95 1632.08,1723.95 1580.08,1749.95 1606.08,1749.95 1632.08,1749.95 1606.08,1775.95 1632.08,1775.95
AVDD12_uFit_SNS: J43.15 R42.2 | length 2107.5
  Bottom Layer w4: v1(1792.71,1191.48) 1762.64,1191.48 1736.93,1165.76 1639.23,1068.07 1524.11,1068.07 1407.26,951.22 1407.26,853.55 1583.35,677.46 1619,641.81 1619,423.57 1718.43,324.14 2497.11,324.14 J43.15@2559.24,262
AVDD18: C110.2 C119.2 C134.2 C135.2 C136.2 C137.2 C148.2 C153.2 C156.2 C157.2 C162.2 C163.2 C164.2 C165.2 C166.2 C168.2 C244.2 FB8.2 FB10.2 J20.3 NT5.2 U1.E9 U1.H5 U1.H13 U1.J13 U1.M6 U1.M13 U1.N1 U1.N6 U1.N13 U1.N17 U1.P6 U1.P13 U1.R6 U1.R13 U1.T1 U1.T3 U1.T4 U1.T14 U1.T15 U1.T17 U3.2 | length 135.7
  L16 PWR/SIG w4: v1(4925.98,1358.27) NT5.2@4934.47,1349.78
  Bottom Layer w8: C148.2@4571.57,1161.34 v1(4579.53,1169.29) ; C153.2@4571.57,1208.72 v1(4579.53,1200.76) ; C163.2@4571.57,1507.79 v1(4579.53,1515.75) ; C162.2@4571.57,1555.2 v1(4579.53,1547.24) ; C137.2@4603.07,1460.71 v1(4611.02,1452.76) ; C136.2@4634.57,1460.71 v1(4642.52,1452.76) ; C135.2@4666.06,1460.71 v1(4674.02,1452.76) ; v1(4674.02,1106.3) C157.2@4681.97,1114.25 ; v1(4674.02,1232.28) C156.2@4681.97,1240.24 ; C134.2@4697.56,1460.71 v1(4705.51,1452.76) ; v1(4925.98,1358.27) C110.2@4933.94,1350.31
  other v1: 2240,818.17 4579.53,1106.3 4611.02,1232.28 4642.52,1232.28 4705.51,1232.28 4800,1232.28 4831.5,1232.28 4831.5,1484.25 4579.53,1610.24 4674.02,1610.24
  other v2: 1468.86,829.11 1494.86,829.11 1520.86,829.11 1468.86,855.11 1494.86,855.11 1468.86,881.61 1494.86,881.11
AVDD18_I2C_SENSE: R174.2 U57.2 | length 319.6
  Top Layer w8: U57.2@1664.82,926.32 1664.82,919.26 1664.76,919.2 1664.1,919.2 1659.35,914.45 1659.35,882.3 1670.42,871.24 1796.52,871.24 1822.44,897.16 1822.44,914.68 1789.28,947.84 R174.2@1759.2,947.84
AVDD18_I-SNS: U31.4 U59.2 | length 434.8
  Top Layer w6: U59.2@1564.23,1296.99 1565.17,1297.93 1565.17,1312.22 v1(1566.2,1313.25)
  L7 SIGNAL w6: v1(1391.13,1000.18) 1446.05,1000.18 1548.06,1102.19 1548.06,1159.89 1566.2,1178.03 v1(1566.2,1313.25)
AVDD18_IN: C243.2 R104.1 R145.2 U31.1 U46.9 U46.10 | length 448.9
  Top Layer w8: v1(1311.5,800.51) 1321.54,800.51 1340.08,819.05 1340.08,864.93 1326.35,878.66 1325.64,878.66 1316.33,887.97 U31.1@1316.33,897.82
  L10 SIGNAL w4: v1(1030,705) 1220.39,705 1229.61,714.22 1306.38,791 1306.38,791.07 1311.5,796.18 v1(1311.5,800.51)
AVDD18_OUT: FB8.1 R104.2 U31.3 U46.8 | length 318.2
  Top Layer w8: R104.2@1381.97,800.51 1373.39,800.51 1355.32,818.59 1355.32,853.87 1380.11,878.66 1381.82,878.66 1391.38,888.23 U31.3@1391.38,897.56
  Top Layer w9: U46.8@1214.61,769.8 1366.73,769.8 1379.72,782.79 1379.72,798.26 R104.2@1381.97,800.51
AVDD18_SENSE: NT5.1 R169.1 R174.1 | length 4078.7
  L16 PWR/SIG w5: v1(1759.2,975.89) 1785.06,975.89 1813.56,1004.39 1826.58,1004.39 1864.06,1041.87 1864.06,1064.98 1902.53,1103.45 2037.32,1103.45 2081.81,1058.96 2142.93,1058.96 2314,887.89 2373.27,887.89 2403.08,917.69 2457.92,917.69 2617.47,1077.24 2683.25,1077.24 2705.97,1054.53 2797.69,1054.53 2820.4,1077.24 2915.57,1077.24 2977.7,1015.11 3293.85,1015.11 3326.68,982.29 3800.61,982.29 3859.61,1041.29 3905.81,1041.29 3925.65,1061.13 4108.38,1061.13 4125.13,1044.38 4131.95,1044.38 4136.5,1039.83 4151.53,1039.83 4186.28,1005.08 4315.4,1005.08 4323.29,1012.98 4502.01,1012.98 4511.01,1021.98 4858.78,1021.98 4889.04,1052.23 4963.25,1052.23 4989.29,1078.27 5057.48,1078.27 5074.65,1095.45 5074.65,1288.76 5052.64,1310.78 4983.05,1310.78 4972.98,1320.85 4972.98,1333.19 4963.9,1342.27 4951.56,1342.27 4946.87,1346.95 NT5.1@4938.01,1346.95
  Bottom Layer w8: R169.1@1747.7,965.89 1748.49,965.89 1758.49,975.89 v1(1759.2,975.89) v1@1759.92,975.89
AVDD18_uFit: FB10.1 J44.1 J44.3
  other v2: 1580.08,823.95 1606.08,823.95 1632.08,823.95 1580.08,849.95 1606.08,849.95 1632.08,849.95 1606.08,875.95 1632.08,875.95
AVDD18_uFit_SNS: J44.5 R169.2 | length 2208.3
  Bottom Layer w4: R169.2@1725.66,965.89 1721.5,961.74 1647.22,961.74 1559.22,873.74 1559.22,735.53 1593.29,701.46 1643,651.75 1643,555.86 1753.16,445.7 2614.38,445.7 2740.39,319.69 3117.4,319.69 3168.69,268.4 J44.5@3168.69,262
CLKIN1_P: C55.2 C70.2 R33.1 R77.2 | length 60
  Bottom Layer w12.1: C55.2@3808.91,2234.21 R77.2@3838.91,2234.21 C70.2@3868.91,2234.21
CLKVDD12: C140.2 C141.2 C237.2 FB3.2 FB7.2 NT3.2 U1.T9 U1.T10 U1.U12 | length 34.5
  L16 PWR/SIG w5: NT3.2@4571.04,1349.78 v1(4579.53,1358.27)
  Bottom Layer w8: C140.2@4571.57,1366.22 v1(4579.53,1358.27) ; v1(4579.53,1326.77) C141.2@4587.48,1318.82
  other v1: 4548.03,1263.78
  other v2: 1468.86,1429.11 1494.86,1429.11 1520.86,1429.11 1468.86,1455.11 1494.86,1455.11 1468.86,1481.61 1494.86,1481.11
CLKVDD12_I2C_SENSE: R172.2 U57.4 | length 279.4
  Top Layer w5: R172.2@1742.87,1105.36 v1(1747.12,1109.61)
  Top Layer w8: U57.4@1704.19,926.32 1704.26,926.26 1704.26,911.4 v1(1713.81,901.85)
  L10 SIGNAL w8: v1@1713.62,901.66 1713.62,967.42 1775.03,1028.84 1775.03,1064.44 1747.12,1092.36 v1(1747.12,1109.61)
CLKVDD12_I-SNS: U32.4 U59.4 | length 837
  Top Layer w6: U32.4@1391.13,1600.18 1742.57,1600.18 1758.78,1583.97 1758.78,1415.25 1714.33,1370.8 1579.93,1370.8 1524.86,1315.74 U59.4@1524.86,1296.99
CLKVDD12_IN: C236.2 R105.1 R139.2 U32.1 U43.9 U43.10 | length 448.9
  Top Layer w8: v1(1311.5,1400.51) 1321.54,1400.51 1340.08,1419.05 1340.08,1464.93 1326.35,1478.66 1325.64,1478.66 1316.33,1487.97 U32.1@1316.33,1497.82
  L10 SIGNAL w4: v1(1030,1305) 1220.39,1305 1229.61,1314.22 1306.38,1391 1306.38,1391.07 1311.5,1396.18 v1(1311.5,1400.51)
CLKVDD12_OUT: FB7.1 R105.2 U32.3 U43.8 | length 319.5
  Top Layer w8: U43.8@1214.61,1369.8 1366.73,1369.8 1379.72,1382.79 1379.72,1398.26 R105.2@1381.97,1400.51 1372.86,1400.51 1354.06,1419.31 1354.06,1452.61 1380.11,1478.66 1381.82,1478.66 1391.38,1488.23 U32.3@1391.38,1497.56
CLKVDD12_SENSE: NT3.1 R167.1 R172.1 | length 3518.1
  Top Layer w5: R172.1@1727.28,1089.77 v1(1723.03,1085.52) 1702.39,1106.16 1702.39,1338.91 1714.08,1350.6 1780.14,1350.6 1808.11,1322.64 1942.3,1322.64 2015.74,1249.2 2460.05,1249.2 2558.28,1347.43 2558.28,1378.17 v1(2542.48,1393.97)
  L16 PWR/SIG w5: v1(2542.48,1393.97) 2546.39,1393.97 2552.91,1387.45 2848.07,1387.45 2940.61,1480 3340.43,1480 3462.15,1358.28 3724.65,1358.28 3759.24,1323.68 3759.24,1292.01 3780.19,1271.06 4280.59,1271.06 4332.85,1323.32 4365.01,1323.32 4417.27,1271.06 4462.72,1271.06 4538.61,1346.95 NT3.1@4568.21,1346.95
  Bottom Layer w8: R167.1@1715.94,1085.52 v1(1723.03,1085.52)
CLKVDD12_uFit: FB3.1 J44.9
  other v2: 1580.08,1423.95 1606.08,1423.95 1632.08,1423.95 1580.08,1449.95 1606.08,1449.95 1632.08,1449.95 1606.08,1475.95 1632.08,1475.95
CLKVDD12_uFit_SNS: J44.11 R167.2 | length 2700.9
  Bottom Layer w4: v1(1686.81,1085.51) 1670.81,1069.51 1670.81,1009.38 1543.22,881.8 1543.22,728.9 1586.66,685.46 1627,645.13 1627,545.05 1745.05,427 2603.69,427 2829.81,200.88 3465.88,200.88 3523.02,258.02 J44.11@3523.02,262
CLKVDD18: C139.2 C142.2 C251.2 FB9.2 FB11.2 NT4.2 U1.T8 U1.T11 | length 23.2
  L16 PWR/SIG w4: NT4.2@4571.04,1286.79 v1(4579.53,1295.28)
  Bottom Layer w8: v1(4579.53,1389.76) C139.2@4587.48,1397.72
  other v2: 1468.86,1129.11 1494.86,1129.11 1520.86,1129.11 1468.86,1155.11 1494.86,1155.11 1468.86,1181.61 1494.86,1181.11
CLKVDD18_I2C_SENSE: R173.2 U57.9 | length 97.2
  Top Layer w8: U57.9@1664.82,959.19 1664.82,1011.47 1680.22,1026.86 1687.34,1026.86 1702.63,1026.86 R173.2@1703.19,1026.31
CLKVDD18_I-SNS: U34.4 U59.9 | length 257.2
  Top Layer w6: U34.4@1391.13,1300.18 1391.13,1290.33 1399.78,1281.69 1415.74,1281.69 1482.66,1214.77 1553.24,1214.77 1564.23,1225.76 U59.9@1564.23,1264.12
CLKVDD18_IN: C250.2 R107.1 R151.2 U34.1 U49.9 U49.10 | length 458.7
  Top Layer w8: v1(1311.5,1100.51) 1321.54,1100.51 1340.08,1119.05 1340.08,1164.93 1326.35,1178.66 1325.64,1178.66 1316.33,1187.97 U34.1@1316.33,1197.82
  L10 SIGNAL w4: v1(1030,1005) 1224.71,1005 1241.71,1022.01 1254,1022.01 1311.5,1079.5 v1(1311.5,1100.51)
CLKVDD18_OUT: FB9.1 R107.2 U34.3 U49.8 | length 319
  Top Layer w8: R107.2@1379.72,1098.26 1381.97,1100.51 1373,1100.51 1354.66,1118.85 1354.66,1153.21 1380.11,1178.66 1381.82,1178.66 1391.38,1188.23 U34.3@1391.38,1197.56
  Top Layer w9: U49.8@1214.61,1069.8 1366.73,1069.8 1379.72,1082.79 R107.2@1379.72,1098.26
CLKVDD18_SENSE: NT4.1 R168.1 R173.1 | length 3488.2
  Top Layer w5: v1(1723.03,1006.47) 1724.53,1007.97 R173.1@1724.53,1011.55 ; R173.1@1723.03,1010.52 1729.12,1016.61 1729.12,1022.19 1706.54,1044.77 1706.54,1078.67 1706.53,1089.19 1693.39,1102.32 1693.39,1255.06 1666.58,1281.88 1666.58,1295.54 1693.39,1322.36 1693.39,1342.64 1710.36,1359.6 1783.87,1359.6 1811.83,1331.64 1946.03,1331.64 2019.47,1258.2 2440.96,1258.2 v1(2541.03,1358.28)
  L16 PWR/SIG w5: v1(2541.03,1358.28) 2880.95,1358.28 2912.2,1389.52 3006.52,1389.52 3018.77,1377.28 3097.86,1377.28 3162.64,1312.5 3162.64,1284.89 3199.53,1248 3422.53,1248 3479.89,1305.36 3733.17,1305.36 3776.47,1262.06 4502.14,1262.06 4519.36,1279.28 4553.96,1279.28 4558.64,1283.96 NT4.1@4568.21,1283.96
  Bottom Layer w8: R168.1@1715.94,1006.45 v1(1723.03,1006.47)
CLKVDD18_uFit: FB11.1 J44.13
  other v2: 1580.08,1123.95 1606.08,1123.95 1632.08,1123.95 1580.08,1149.95 1606.08,1149.95 1632.08,1149.95 1606.08,1175.95 1632.08,1175.95
CLKVDD18_uFit_SNS: J44.15 R168.2 | length 2916.8
  Bottom Layer w4: 1589.97,693.46 1551.22,732.22 1551.22,877.06 1677.54,1003.37 1683.75,1003.37 v1(1686.81,1006.44) ; 1589.97,693.46 1635,648.44 1635,549.67 1749.67,435 2609.14,435 2829.1,215.04 3435.04,215.04 3460,240 3460,300 3480,320 3701.24,320 J44.15@3759.24,262
CSb_LMK: J21.5 U2.18 U6.5 | length 4229.1
  L16 PWR/SIG w5: v1(1116.3,2400.75) 1148.16,2432.6 1148.16,2466.24 1116.3,2498.09 1116.3,2589.03 1198.31,2671.04 3321.36,2671.04 3352.65,2639.74 3352.65,2436.06 3402.83,2385.88 3687.31,2385.88 3889.47,2588.04 3895.77,2588.04 3958.42,2650.7 J21.5@4210.66,2650.7
  L10 SIGNAL w5: J21.5@4210.66,2650.7 4205.38,2645.43 4205.38,2439.21 4208.08,2436.52 4208.08,2259.8 4222.14,2245.74 v1(4222.14,2170.43)
  Bottom Layer w8: U6.5@1091.98,2390.75 1106.98,2390.75 1113.9,2397.66 1113.9,2398.45 1116.19,2400.75 v1(1116.3,2400.75) v1@1116.98,2400.75
  Bottom Layer w10: v1(4222.14,2170.43) U2.18@4222.14,2190.43
CSb_LMK_FMC_3p3V: U6.4 U15.11 | length 219.6
  Bottom Layer w8: U6.4@1068.36,2398.62 1068.36,2413.62 1083.36,2428.62 1154.99,2428.62 1215.11,2368.5 U15.11@1241.86,2368.5
CSb_LMK_FMC_VADJ: J29.G16 U15.2 U17.1 | length 6050
  Top Layer w5: v1(1337.89,2373.5) 1354.17,2373.5 1370.63,2357.05 v1(1370.63,2303.62)
  L16 PWR/SIG w5: v1(1337.89,2373.5) 1352.85,2388.46 1352.85,2409.89 1303.74,2459 1193.58,2459 1143.3,2509.28 1143.3,2577.85 1209.49,2644.04 2540.93,2644.04 2557.97,2626.99 2557.97,2463.36 2592.33,2429 3321.52,2429 3393.52,2357 4435.95,2357 4602.48,2190.47 4633,2190.47 4669.8,2153.67 5224.6,2153.67 5363.68,2014.59 5372.67,2005.6 5545.53,1832.74 5570.5,1807.77 5707.84,1807.77 5756.97,1758.63 5778.07,1758.63 5790,1746.71 5790,1726.72 5773,1709.72 5742.71,1709.72 5728.24,1724.19 5728.24,1738.78 5717.39,1749.63 5701.34,1749.63 5690.01,1738.31 5690.01,1677.09 5709.34,1657.77 5775.03,1657.77 5790,1642.8 5790,1616.77 5765.83,1592.6 5765.83,1590.74 5761.42,1586.33 v1(5761.42,1582.27)
  Bottom Layer w8: U15.2@1304.86,2368.5 v1@1329.64,2368.5 ; v1(1370.63,2303.62) 1370.63,2302.94 1380.63,2292.94 U17.1@1380.63,2283.62
CSb_LMK_USB: J28.29 U6.3 | length 685.3
  Top Layer w8: J28.29@564.06,2395 v1(564.06,2475)
  L16 PWR/SIG w5: v1(564.06,2475) 599.06,2510 902.82,2510 1009.21,2403.6 1033.93,2403.6 1057.61,2427.28 v1(1057.61,2433.62)
  Bottom Layer w8: U6.3@1052.61,2398.62 1052.61,2425.37 1057.61,2430.37 v1(1057.61,2433.62)
DCLKA_N: J29.D21 U1.F17 | length 3132
  L7 SIGNAL w3.5: v1(4894.49,1106.3) 4905.24,1095.55 4905.24,1045.11 4911.09,1039.25 4931.73,1018.61 4932.48,1017.86 4932.48,959.91 4976.63,915.77 5045.33,915.77 5068.5,892.6 5098.74,862.36 5159.63,801.46 5929.67,801.46 5946.67,818.47 5946.67,847.08 5928.75,865 5329.8,865 5305.42,889.38 5305.42,896.94 5309.45,900.97 5917.97,900.97 5944,927 5944,1297.02 5931.68,1309.34 5884.05,1309.34 5873,1320.39 5873,1349 5876.27,1352.27 5907.88,1352.27 5909.93,1350.22 5909.93,1333.76 v1(5911.42,1332.27)
DCLKA_P: J29.D20 U1.E17 | length 3130.4
  L7 SIGNAL w3.5: v1(4925.98,1106.3) 4915.24,1095.55 4915.24,1049.25 4941.73,1022.75 4942.48,1022 4942.48,964.06 4980.77,925.77 5049.47,925.77 5078.5,896.74 5105.81,869.43 5163.77,811.46 5189.42,811.46 5192,814.04 5202.74,814.04 5205.32,811.46 5216.06,811.46 5218.64,814.04 5229.37,814.04 5231.95,811.46 5242.69,811.46 5245.27,814.04 5256.01,814.04 5258.59,811.46 5272.65,811.46 5275.23,814.04 5285.97,814.04 5288.55,811.46 5302.61,811.46 5305.19,814.04 5315.92,814.04 5318.5,811.46 5332.56,811.46 5335.14,814.04 5345.88,814.04 5348.46,811.46 5362.52,811.46 5365.1,814.04 5375.84,814.04 5378.42,811.46 5925.53,811.46 5936.67,822.61 5936.67,842.94 5924.61,855 5325.65,855 5298.34,882.31 5295.42,885.24 5295.42,901.08 5305.3,910.97 5913.83,910.97 5934,931.14 5934,1292.88 5927.54,1299.34 5879.9,1299.34 5863,1316.24 5863,1353.14 5872.13,1362.27 5907.88,1362.27 5909.93,1364.32 5909.93,1380.78 v1(5911.42,1382.27)
DCLKB_N: J29.F4 U1.F1 | length 1597
  L12 SIGNAL w3.5: v1(4894.49,1610.24) 4905.24,1620.98 4905.24,1653.8 4951.85,1700.41 4976.82,1700.41 4977.38,1699.85 5085.71,1699.85 5125.68,1739.82 5128.99,1743.13 5128.99,1762.18 5119.69,1771.48 5119.69,1798.82 5133.71,1812.85 5161.05,1812.85 5185.08,1788.82 5204.14,1788.82 5212.31,1796.98 5212.31,1816.04 5188.27,1840.07 5188.27,1867.41 5202.3,1881.44 5229.64,1881.44 5253.67,1857.41 5272.73,1857.41 5280.9,1865.57 5280.9,1884.63 5256.86,1908.66 5256.86,1936 5270.89,1950.03 5298.23,1950.03 5322.26,1925.99 5341.32,1925.99 5349.49,1934.16 5349.49,1953.22 5325.45,1977.25 5325.45,2004.59 5339.48,2018.62 5366.82,2018.62 5390.85,1994.58 5409.91,1994.58 5418.07,2002.75 5418.07,2021.81 5401.52,2038.36 5401.52,2065.7 5415.55,2079.73 5442.89,2079.73 5444.71,2077.91 5463.76,2077.91 5511.44,2125.59 5517.68,2131.82 5548.13,2162.27 5809.37,2162.27 5811.42,2164.32 v1(5811.42,2182.27)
